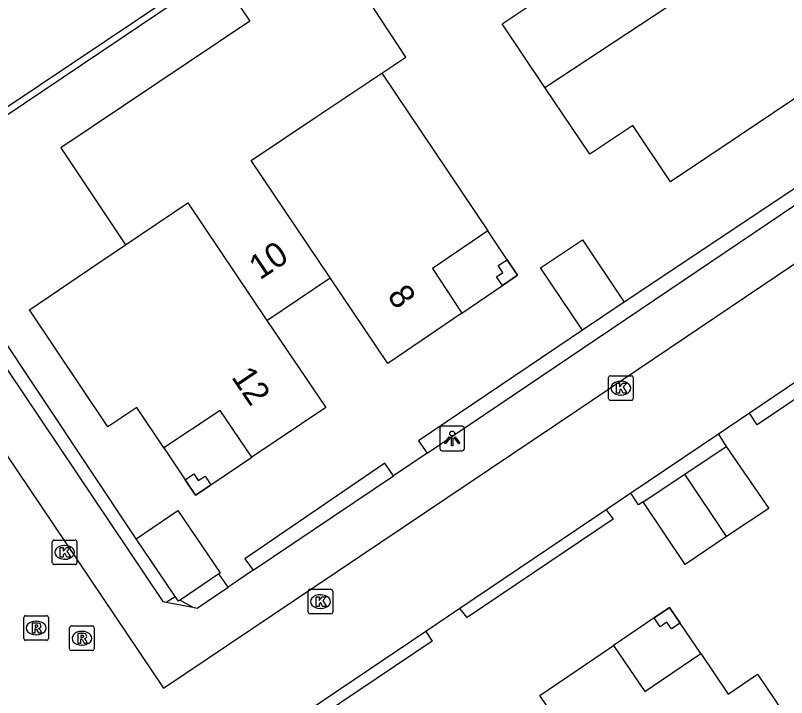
# Model space of a CAD drawing. Extents: x 158797 to 159887, y 384318 to 385255.
# Drawn here: x 159017.41 to 159048.69, y 384665 to 384692.68 of the extents above; entities that cross this region are included whole.
import ezdxf

# ---------------------------------------------------------------- set-up
doc = ezdxf.new("R2010")
doc.units = 0
for name, color, linetype in [('IMGEO_Haag', 7, 'Continuous'), ('IMGEO_Kolk', 7, 'Continuous'), ('IMGEO_Lichtpunt', 7, 'Continuous'), ('IMGEO_Pand', 7, 'Continuous'), ('IMGEO_Pand_nummerreeks', 7, 'Continuous'), ('IMGEO_Pand_overbouw', 7, 'Continuous'), ('IMGEO_Parkeervlak_open', 7, 'Continuous'), ('IMGEO_Rijbaan_lokaal_open', 7, 'Continuous'), ('IMGEO_Rioolput', 7, 'Continuous'), ('IMGEO_Voetpad_open', 7, 'Continuous')]:
    doc.layers.add(name, color=color, linetype=linetype)

msp = doc.modelspace()

# ---------------------------------------------------------------- linework, layer by layer
at = {"layer": 'IMGEO_Haag'}
for points in [[(159016.845, 384688.805), (159016.999, 384688.587), (159030.87, 384697.932), (159024.718, 384707.573), (159022.492, 384711.051), (159035.359, 384719.573)], [(159055.316, 384689.846), (159042.109, 384681.044)], [(159061.91, 384685.784), (159047.504, 384676.068), (159047.185, 384676.54)], [(159022.309, 384671.435), (159014.649, 384682.946)], [(159040.42, 384679.911), (159033.762, 384675.419), (159034.111, 384674.923)], [(159045.929, 384675.692), (159046.249, 384675.19)], [(159032.743, 384674), (159032.394, 384674.514), (159026.725, 384670.624), (159027.054, 384670.164)], [(159042.883, 384672.937), (159042.686, 384672.823), (159042.383, 384673.3)], [(159041.379, 384672.623), (159041.663, 384672.233), (159035.739, 384668.252), (159035.442, 384668.618)], [(159026.047, 384669.485), (159025.667, 384670.027)], [(159023.532, 384668.866), (159023.895, 384669.096)], [(159024.09, 384668.958), (159024.609, 384668.666)], [(159034.06, 384667.685), (159034.319, 384667.294), (159028.291, 384663.236), (159028.043, 384663.626)]]:
    msp.add_lwpolyline(points, dxfattribs=at)
at = {"layer": 'IMGEO_Kolk'}
for p, q in [((159041.472, 384677.13), (159041.472, 384677.982)), ((159041.547, 384678.056), (159042.399, 384678.056)), ((159041.96, 384677.836), (159041.985, 384677.836)), ((159042.473, 384677.982), (159042.473, 384677.13)), ((159041.983, 384677.276), (159041.958, 384677.276)), ((159042.399, 384677.056), (159041.547, 384677.056)), ((159018.909, 384670.467), (159018.909, 384671.319)), ((159018.984, 384671.393), (159019.836, 384671.393)), ((159019.91, 384671.319), (159019.91, 384670.467)), ((159019.397, 384671.173), (159019.422, 384671.173)), ((159019.836, 384670.393), (159018.984, 384670.393)), ((159019.42, 384670.613), (159019.395, 384670.613)), ((159029.361, 384669.392), (159030.213, 384669.392)), ((159029.286, 384668.466), (159029.286, 384669.318)), ((159029.774, 384669.172), (159029.799, 384669.172)), ((159030.287, 384669.318), (159030.287, 384668.466)), ((159029.797, 384668.612), (159029.772, 384668.612)), ((159030.213, 384668.392), (159029.361, 384668.392))]:
    msp.add_line(p, q, dxfattribs=at)
for points in [[(159041.472, 384677.13), (159041.472, 384677.982)], [(159041.547, 384678.056), (159042.399, 384678.056)], [(159042.473, 384677.982), (159042.473, 384677.13)], [(159041.793, 384677.756), (159041.916, 384677.756), (159041.916, 384677.605), (159042.046, 384677.756), (159042.21, 384677.756), (159042.064, 384677.605), (159042.217, 384677.356), (159042.065, 384677.356), (159041.98, 384677.52), (159041.916, 384677.453), (159041.916, 384677.356), (159041.793, 384677.356), (159041.793, 384677.756)], [(159042.399, 384677.056), (159041.547, 384677.056)], [(159018.909, 384670.467), (159018.909, 384671.319)], [(159018.984, 384671.393), (159019.836, 384671.393)], [(159019.91, 384671.319), (159019.91, 384670.467)], [(159019.23, 384671.093), (159019.353, 384671.093), (159019.353, 384670.942), (159019.483, 384671.093), (159019.647, 384671.093), (159019.501, 384670.942), (159019.654, 384670.693), (159019.502, 384670.693), (159019.417, 384670.857), (159019.353, 384670.79), (159019.353, 384670.693), (159019.23, 384670.693), (159019.23, 384671.093)], [(159019.836, 384670.393), (159018.984, 384670.393)], [(159029.361, 384669.392), (159030.213, 384669.392)], [(159029.286, 384668.466), (159029.286, 384669.318)], [(159029.607, 384669.092), (159029.73, 384669.092), (159029.73, 384668.941), (159029.86, 384669.092), (159030.024, 384669.092), (159029.878, 384668.941), (159030.031, 384668.692), (159029.879, 384668.692), (159029.794, 384668.856), (159029.73, 384668.789), (159029.73, 384668.692), (159029.607, 384668.692), (159029.607, 384669.092)], [(159030.287, 384669.318), (159030.287, 384668.466)], [(159030.213, 384668.392), (159029.361, 384668.392)]]:
    msp.add_lwpolyline(points, dxfattribs=at)
for centre, start, end in [((159041.549, 384677.98), 91.552, 178.448), ((159041.549, 384677.98), 91.552, 178.448), ((159042.397, 384677.98), 1.552, 88.448), ((159042.397, 384677.98), 1.552, 88.448), ((159041.549, 384677.132), 181.552, 268.448), ((159041.549, 384677.132), 181.552, 268.448), ((159042.397, 384677.132), 271.552, 358.448), ((159042.397, 384677.132), 271.552, 358.448), ((159018.986, 384671.317), 91.552, 178.448), ((159018.986, 384671.317), 91.552, 178.448), ((159019.834, 384671.317), 1.552, 88.448), ((159019.834, 384671.317), 1.552, 88.448), ((159018.986, 384670.469), 181.552, 268.448), ((159018.986, 384670.469), 181.552, 268.448), ((159019.834, 384670.469), 271.552, 358.448), ((159019.834, 384670.469), 271.552, 358.448), ((159029.363, 384669.316), 91.552, 178.448), ((159029.363, 384669.316), 91.552, 178.448), ((159030.211, 384669.316), 1.552, 88.448), ((159030.211, 384669.316), 1.552, 88.448), ((159029.363, 384668.468), 181.552, 268.448), ((159029.363, 384668.468), 181.552, 268.448), ((159030.211, 384668.468), 271.552, 358.448), ((159030.211, 384668.468), 271.552, 358.448)]:
    msp.add_arc(centre, 0.0765, start, end, dxfattribs=at)
for centre, major_axis, ratio, start_param, end_param in [((159041.959, 384677.556), (-0.387, 0.002), 0.722429, 4.712389, 7.853982), ((159041.984, 384677.556), (-0.39, 0.002), 0.717154, 1.570796, 4.712389), ((159019.396, 384670.893), (-0.387, 0.002), 0.722429, 4.712389, 7.853982), ((159019.421, 384670.893), (-0.39, 0.002), 0.717154, 1.570796, 4.712389), ((159029.773, 384668.892), (-0.387, 0.002), 0.722429, 4.712389, 7.853982), ((159029.798, 384668.892), (-0.39, 0.002), 0.717154, 1.570796, 4.712389)]:
    msp.add_ellipse(centre, major_axis=major_axis, ratio=ratio, start_param=start_param, end_param=end_param, dxfattribs=at)
at = {"layer": 'IMGEO_Lichtpunt'}
for p, q in [((159035.531, 384676.011), (159034.723, 384676.011)), ((159035.531, 384676.011), (159034.723, 384676.011)), ((159034.629, 384675.916), (159034.629, 384675.109)), ((159034.629, 384675.916), (159034.629, 384675.109)), ((159035.625, 384675.109), (159035.625, 384675.916)), ((159035.625, 384675.109), (159035.625, 384675.916)), ((159034.723, 384675.015), (159035.531, 384675.015)), ((159034.723, 384675.015), (159035.531, 384675.015))]:
    msp.add_line(p, q, dxfattribs=at)
for points in [[(159035.003, 384675.58), (159035.042, 384675.552), (159034.854, 384675.29), (159034.816, 384675.317), (159035.003, 384675.58)], [(159035.105, 384675.532), (159035.152, 384675.532), (159035.152, 384675.21), (159035.105, 384675.21), (159035.105, 384675.532)], [(159035.215, 384675.552), (159035.253, 384675.579), (159035.44, 384675.317), (159035.401, 384675.289), (159035.215, 384675.552)]]:
    msp.add_lwpolyline(points, dxfattribs=at)
msp.add_circle((159035.128, 384675.714), 0.0994, dxfattribs=at)
for centre, start, end in [((159034.723, 384675.916), 90, 180), ((159034.723, 384675.916), 90, 180), ((159035.531, 384675.916), 0, 90), ((159035.531, 384675.916), 0, 90), ((159034.723, 384675.109), 180, 270), ((159034.723, 384675.109), 180, 270), ((159035.531, 384675.109), 270, 0), ((159035.531, 384675.109), 270, 360)]:
    msp.add_arc(centre, 0.0946, start, end, dxfattribs=at)
at = {"layer": 'IMGEO_Pand'}
for points in [[(159038.89, 384689.755), (159037.159, 384692.334), (159038.938, 384693.537), (159036.601, 384696.993), (159041.436, 384700.241), (159042.229, 384699.061), (159045.709, 384701.391), (159047.656, 384698.482), (159046.366, 384697.618), (159047.711, 384695.583)], [(159032.277, 384690.34), (159033.245, 384690.989), (159029.956, 384696.009), (159026.219, 384693.503), (159026.926, 384692.448), (159019.249, 384687.3), (159021.88, 384683.374)], [(159047.711, 384695.583), (159049.055, 384693.548), (159050.34, 384694.411), (159052.295, 384691.502), (159043.979, 384685.926), (159042.461, 384688.214), (159040.71, 384687.044), (159038.89, 384689.755)], [(159038.89, 384689.755), (159047.711, 384695.583)], [(159030.179, 384682.029), (159026.979, 384686.789), (159029.561, 384688.519), (159032.277, 384690.34)], [(159032.277, 384690.34), (159036.569, 384683.938), (159034.328, 384682.412), (159035.518, 384680.598), (159032.519, 384678.557), (159030.179, 384682.029)], [(159021.88, 384683.374), (159024.41, 384685.069), (159027.613, 384680.304)], [(159040.42, 384679.911), (159038.718, 384682.441), (159040.412, 384683.578), (159042.109, 384681.044)], [(159027.613, 384680.304), (159030, 384676.764), (159027.005, 384674.748), (159025.717, 384676.65), (159023.432, 384675.127), (159022.331, 384676.771), (159021.158, 384675.986), (159017.982, 384680.739), (159020.712, 384682.584), (159021.88, 384683.374)], [(159037.354, 384682.766), (159037.777, 384682.135), (159037.166, 384681.719), (159036.921, 384682.072), (159037.181, 384682.253), (159036.997, 384682.527), (159037.354, 384682.766)], [(159027.613, 384680.304), (159028.896, 384681.167), (159030.179, 384682.029)], [(159042.109, 384681.044), (159040.42, 384679.911)], [(159044.566, 384674.064), (159046.249, 384675.19)], [(159046.249, 384675.19), (159047.974, 384672.672), (159046.262, 384671.529)], [(159025.342, 384673.628), (159025.232, 384673.555), (159024.716, 384673.207), (159024.294, 384673.839), (159024.651, 384674.078), (159024.831, 384673.809), (159025.107, 384673.988), (159025.342, 384673.628)], [(159042.883, 384672.937), (159044.566, 384674.064)], [(159046.262, 384671.529), (159044.566, 384674.064)], [(159046.262, 384671.529), (159044.578, 384670.405), (159042.883, 384672.937)], [(159022.309, 384671.435), (159024.006, 384672.586), (159025.72, 384670.063), (159025.667, 384670.027)], [(159023.895, 384669.096), (159022.309, 384671.435)], [(159025.667, 384670.027), (159024.09, 384668.958)], [(159024.09, 384668.958), (159024.021, 384668.911), (159023.895, 384669.096)], [(159044.02, 384667.785), (159043.836, 384668.058), (159043.562, 384667.873), (159043.321, 384668.229), (159043.951, 384668.655), (159044.377, 384668.025), (159044.02, 384667.785)], [(159041.107, 384661.511), (159038.68, 384665.087), (159041.675, 384667.115), (159042.943, 384665.247), (159045.213, 384666.788), (159046.326, 384665.143), (159047.517, 384665.945), (159050.714, 384661.196), (159046.795, 384658.552)]]:
    msp.add_lwpolyline(points, dxfattribs=at)
at = {"layer": 'IMGEO_Pand_overbouw'}
for points in [[(159037.166, 384681.719), (159037.777, 384682.135), (159037.354, 384682.766), (159036.569, 384683.938), (159034.328, 384682.412), (159035.518, 384680.598)], [(159027.005, 384674.748), (159025.717, 384676.65), (159023.432, 384675.127), (159024.294, 384673.839), (159024.716, 384673.207), (159025.232, 384673.555), (159025.342, 384673.628)], [(159041.675, 384667.115), (159042.943, 384665.247), (159045.213, 384666.788), (159044.377, 384668.025), (159043.951, 384668.655), (159043.321, 384668.229)]]:
    msp.add_lwpolyline(points, close=True, dxfattribs=at)
at = {"layer": 'IMGEO_Parkeervlak_open'}
msp.add_lwpolyline([(159027.614, 384696.029), (159017.072, 384688.957)], dxfattribs=at)
at = {"layer": 'IMGEO_Rijbaan_lokaal_open'}
for points in [[(159007.469, 384689.118), (159015.48, 384677.168), (159023.424, 384665.376), (159040.186, 384676.652), (159060.67, 384690.454)], [(159063.78, 384687.735), (159057.782, 384683.689), (159047.185, 384676.54)], [(159047.185, 384676.54), (159045.929, 384675.692)], [(159045.929, 384675.692), (159042.383, 384673.3)], [(159042.383, 384673.3), (159041.379, 384672.623)], [(159041.379, 384672.623), (159035.442, 384668.618)], [(159035.442, 384668.618), (159034.06, 384667.685)], [(159034.06, 384667.685), (159028.043, 384663.626)]]:
    msp.add_lwpolyline(points, dxfattribs=at)
at = {"layer": 'IMGEO_Rioolput'}
for p, q in [((159017.752, 384667.397), (159017.752, 384668.249)), ((159017.827, 384668.323), (159018.679, 384668.323)), ((159018.753, 384668.249), (159018.753, 384667.397)), ((159018.24, 384668.103), (159018.265, 384668.103)), ((159019.609, 384666.979), (159019.609, 384667.831)), ((159019.684, 384667.905), (159020.536, 384667.905)), ((159020.61, 384667.831), (159020.61, 384666.979)), ((159018.263, 384667.543), (159018.238, 384667.543)), ((159020.097, 384667.685), (159020.122, 384667.685)), ((159018.679, 384667.323), (159017.827, 384667.323)), ((159020.536, 384666.905), (159019.684, 384666.905)), ((159020.12, 384667.125), (159020.095, 384667.125))]:
    msp.add_line(p, q, dxfattribs=at)
for points in [[(159017.752, 384667.397), (159017.752, 384668.249)], [(159017.827, 384668.323), (159018.679, 384668.323)], [(159018.753, 384668.249), (159018.753, 384667.397)], [(159018.341, 384668.021), (159018.089, 384668.023), (159018.089, 384667.623)], [(159018.267, 384667.942), (159018.213, 384667.942), (159018.213, 384667.861)], [(159018.213, 384667.861), (159018.265, 384667.861)], [(159019.609, 384666.979), (159019.609, 384667.831)], [(159019.684, 384667.905), (159020.536, 384667.905)], [(159020.61, 384667.831), (159020.61, 384666.979)], [(159018.089, 384667.623), (159018.213, 384667.623), (159018.213, 384667.785), (159018.224, 384667.785)], [(159018.271, 384667.756), (159018.342, 384667.623), (159018.482, 384667.623), (159018.417, 384667.749)], [(159020.198, 384667.603), (159019.946, 384667.605), (159019.946, 384667.205)], [(159020.124, 384667.524), (159020.07, 384667.524), (159020.07, 384667.443)], [(159018.679, 384667.323), (159017.827, 384667.323)], [(159019.946, 384667.205), (159020.07, 384667.205), (159020.07, 384667.367), (159020.081, 384667.367)], [(159020.07, 384667.443), (159020.122, 384667.443)], [(159020.128, 384667.338), (159020.199, 384667.205), (159020.339, 384667.205), (159020.274, 384667.331)], [(159020.536, 384666.905), (159019.684, 384666.905)]]:
    msp.add_lwpolyline(points, dxfattribs=at)
for centre, radius, start, end in [((159017.829, 384668.247), 0.0765, 91.552, 178.448), ((159017.829, 384668.247), 0.0765, 91.552, 178.448), ((159018.677, 384668.247), 0.0765, 1.552, 88.448), ((159018.677, 384668.247), 0.0765, 1.552, 88.448), ((159018.249, 384668.05), 0.19, 274.7715, 282.9687), ((159018.273, 384667.846), 0.0964, 77.0061, 93.1865), ((159018.287, 384667.903), 0.0378, 276.6634, 79.6772), ((159018.34, 384667.911), 0.109, 350.3612, 89.416), ((159018.338, 384667.911), 0.112, 277.5842, 350.9817), ((159019.686, 384667.829), 0.0765, 91.552, 178.448), ((159019.686, 384667.829), 0.0765, 91.552, 178.448), ((159020.534, 384667.829), 0.0765, 1.552, 88.448), ((159020.534, 384667.829), 0.0765, 1.552, 88.448), ((159018.223, 384667.732), 0.0533, 26.0293, 88.6989), ((159018.322, 384667.696), 0.108, 29.5134, 73.7905), ((159020.13, 384667.428), 0.0964, 77.0061, 93.1865), ((159020.144, 384667.485), 0.0378, 276.6634, 79.6772), ((159020.197, 384667.493), 0.109, 350.3612, 89.416), ((159017.829, 384667.399), 0.0765, 181.552, 268.448), ((159017.829, 384667.399), 0.0765, 181.552, 268.448), ((159018.677, 384667.399), 0.0765, 271.552, 358.448), ((159018.677, 384667.399), 0.0765, 271.552, 358.448), ((159020.08, 384667.314), 0.0533, 26.0293, 88.6989), ((159020.106, 384667.632), 0.19, 274.7715, 282.9687), ((159020.195, 384667.493), 0.112, 277.5842, 350.9817), ((159020.179, 384667.278), 0.108, 29.5134, 73.7905), ((159019.686, 384666.981), 0.0765, 181.552, 268.448), ((159019.686, 384666.981), 0.0765, 181.552, 268.448), ((159020.534, 384666.981), 0.0765, 271.552, 358.448), ((159020.534, 384666.981), 0.0765, 271.552, 358.448)]:
    msp.add_arc(centre, radius, start, end, dxfattribs=at)
for centre, major_axis, ratio, start_param, end_param in [((159018.239, 384667.823), (-0.387, 0.002), 0.722429, 4.712389, 7.853982), ((159018.264, 384667.823), (-0.39, 0.002), 0.717154, 1.570796, 4.712389), ((159020.096, 384667.405), (-0.387, 0.002), 0.722429, 4.712389, 7.853982), ((159020.121, 384667.405), (-0.39, 0.002), 0.717154, 1.570796, 4.712389)]:
    msp.add_ellipse(centre, major_axis=major_axis, ratio=ratio, start_param=start_param, end_param=end_param, dxfattribs=at)
at = {"layer": 'IMGEO_Voetpad_open'}
for points in [[(159034.111, 384674.923), (159057.126, 384690.444)], [(159012.161, 384685.634), (159023.393, 384668.892), (159023.532, 384668.866)], [(159034.111, 384674.923), (159032.743, 384674)], [(159027.054, 384670.164), (159032.743, 384674)], [(159027.054, 384670.164), (159026.047, 384669.485)], [(159024.609, 384668.666), (159024.784, 384668.633), (159026.047, 384669.485)], [(159023.532, 384668.866), (159024.609, 384668.666)]]:
    msp.add_lwpolyline(points, dxfattribs=at)

# ---------------------------------------------------------------- texts
at = {"layer": 'IMGEO_Pand_nummerreeks'}
for s, rotation, p in [('10', 33.9134, (159027.329, 384681.921)), ('8', 303.9762, (159032.47, 384681.314)), ('12', 303.9934, (159026.15, 384678.002))]:
    msp.add_text(s, height=1, rotation=rotation, dxfattribs=at).set_placement(p)

doc.saveas('drawing.dxf')
